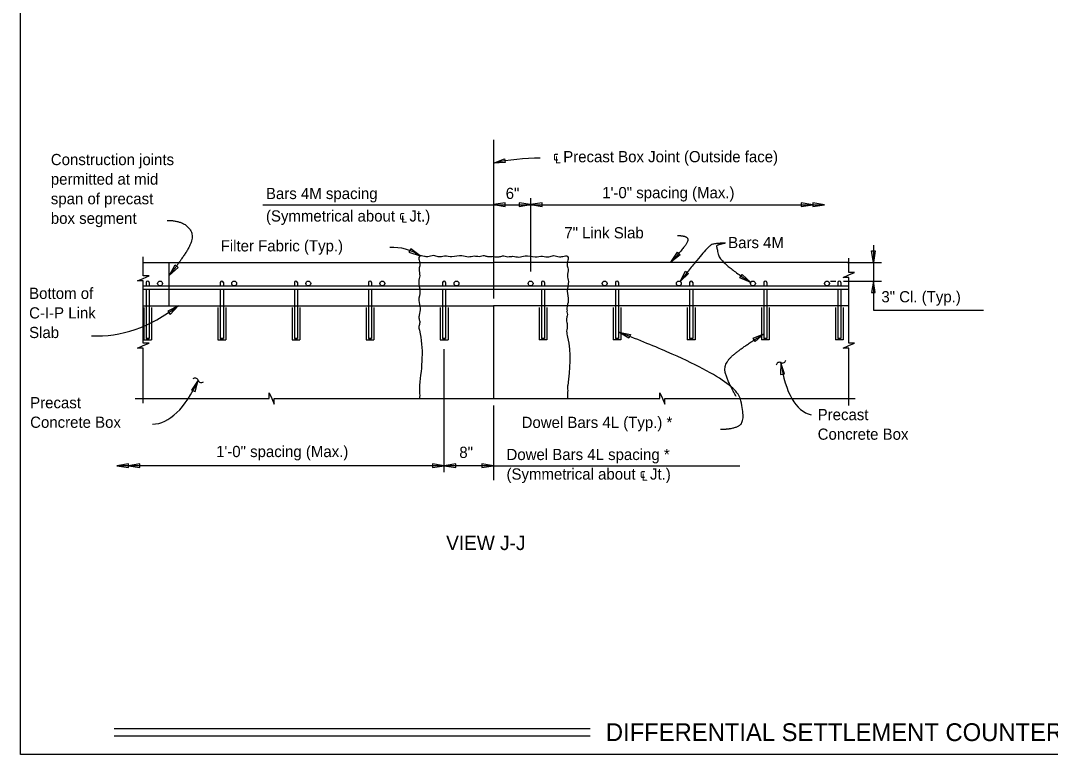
# Model space of a CAD drawing. Extents: x 0 to 30.8, y 0 to 19.8.
# Drawn here: x 0 to 13.9, y 0 to 9.9 of the extents above; entities that cross this region are included whole.
import ezdxf

# ---------------------------------------------------------------- set-up
doc = ezdxf.new("R2010")
doc.units = 0
for name, color, linetype in [('CL_Major', 7, 'Continuous'), ('Dimension', 7, 'Continuous'), ('Miscellaneous', 7, 'Continuous'), ('Miscellaneous1', 7, 'Continuous'), ('Rebar', 7, 'Continuous'), ('SubStrConc', 7, 'Continuous'), ('SubStrConc_h', 7, 'Continuous'), ('TextStructures', 7, 'Continuous')]:
    doc.layers.add(name, color=color, linetype=linetype)

msp = doc.modelspace()

# ---------------------------------------------------------------- linework, layer by layer
at = {"layer": 'CL_Major'}
for p, q in [((6.382, 8.293), (6.382, 6.152)), ((6.382, 4.707), (6.382, 3.699))]:
    msp.add_line(p, q, dxfattribs=at)
at = {"layer": 'Dimension'}
for p, q in [((3.267, 7.416), (6.382, 7.416)), ((6.382, 7.416), (10.846, 7.416)), ((6.882, 7.504), (6.882, 6.514)), ((11.508, 6.872), (11.508, 5.993)), ((11.16, 6.636), (11.618, 6.636)), ((10.929, 6.386), (11, 6.386)), ((11.106, 6.386), (11.618, 6.386)), ((11.508, 5.993), (12.995, 5.993)), ((5.715, 3.808), (5.715, 5.465)), ((6.382, 3.895), (1.299, 3.895)), ((6.382, 3.895), (9.705, 3.895)), ((1.261, 0.35), (7.688, 0.35)), ((1.261, 0.25), (7.688, 0.25))]:
    msp.add_line(p, q, dxfattribs=at)
for points in [[(0, 19.46), (30.788, 19.46), (30.788, 0), (0, 0)], [(6.382, 7.977), (6.529, 8.036), (6.54, 7.984)], [(6.382, 7.417), (6.538, 7.39), (6.538, 7.443)], [(6.882, 7.417), (6.726, 7.443), (6.726, 7.39)], [(6.882, 7.417), (7.038, 7.39), (7.038, 7.443)], [(10.69, 7.416), (10.534, 7.443), (10.534, 7.39)], [(10.846, 7.416), (10.69, 7.443), (10.69, 7.39)], [(5.391, 6.726), (5.266, 6.823), (5.241, 6.776)], [(8.902, 6.738), (8.775, 6.643), (8.863, 6.774)], [(11.508, 6.636), (11.482, 6.792), (11.534, 6.792)], [(2.127, 6.57), (2.008, 6.466), (2.086, 6.603)], [(9.015, 6.488), (8.899, 6.38), (8.974, 6.52)], [(9.735, 6.476), (9.852, 6.368), (9.706, 6.431)], [(11.508, 6.386), (11.482, 6.23), (11.534, 6.23)], [(2.126, 6.052), (1.985, 5.979), (2.018, 5.937)], [(8.209, 5.616), (8.073, 5.697), (8.228, 5.666)], [(9.885, 5.616), (10.031, 5.675), (9.912, 5.571)], [(10.261, 5.285), (10.256, 5.127), (10.309, 5.134)], [(2.395, 5.047), (2.307, 4.916), (2.355, 4.894)], [(1.299, 3.895), (1.455, 3.869), (1.455, 3.922)], [(1.455, 3.895), (1.611, 3.869), (1.611, 3.922)], [(5.715, 3.895), (5.559, 3.922), (5.559, 3.869)], [(5.715, 3.895), (5.872, 3.869), (5.872, 3.922)], [(6.382, 3.895), (6.226, 3.922), (6.226, 3.869)]]:
    msp.add_lwpolyline(points, close=True, dxfattribs=at)
for points in [[(1.656, 6.052), (1.656, 6.387), (1.578, 6.387), (1.656, 6.421), (1.733, 6.455), (1.656, 6.455), (1.656, 6.714)], [(11.175, 6.052), (11.175, 6.435), (11.098, 6.435), (11.175, 6.469), (11.253, 6.502), (11.175, 6.502), (11.175, 6.696)], [(1.656, 4.737), (1.656, 5.482), (1.578, 5.482), (1.656, 5.516), (1.733, 5.55), (1.656, 5.55), (1.656, 6.052)], [(11.175, 4.706), (11.175, 5.482), (11.098, 5.482), (11.175, 5.516), (11.253, 5.55), (11.175, 5.55), (11.175, 6.052)], [(1.547, 4.801), (3.356, 4.801), (3.356, 4.878), (3.39, 4.801), (3.423, 4.723), (3.423, 4.801), (6.382, 4.801)], [(6.382, 4.801), (8.627, 4.801), (8.627, 4.878), (8.66, 4.801), (8.694, 4.723), (8.694, 4.801), (11.263, 4.801)]]:
    msp.add_lwpolyline(points, dxfattribs=at)
for centre, radius, start, end in [((7.023, 5.008), 3.037, 90.1862, 102.1882), ((5.02, 6.182), 0.658, 55.6058, 93.4311), ((10.24, 5.246), 0.0447, 61.6836, 173.4108), ((10.282, 5.325), 0.0447, 241.6836, 353.4108), ((2.353, 5.032), 0.0447, 19.8148, 131.542), ((2.437, 5.062), 0.0447, 199.8148, 311.542)]:
    msp.add_arc(centre, radius, start, end, dxfattribs=at)
for centre, major_axis, ratio, start_param, end_param in [((1.12, 13.945), (0.099, 8.299), 0.422031, 3.123668, 3.460947), ((11.093, 6.474), (0.427, 1.891), 0.393692, 2.335904, 3.141593), ((1.717, 7.141), (-0.061, 2.686), 0.379091, 3.141593, 3.809705)]:
    msp.add_ellipse(centre, major_axis=major_axis, ratio=ratio, start_param=start_param, end_param=end_param, dxfattribs=at)
for points in [[(1.98, 7.204), (2.186, 7.204), (2.361, 6.994), (2.166, 6.66), (2.008, 6.466)], [(8.866, 7), (9.005, 7), (9.005, 6.885), (8.775, 6.643)], [(9.511, 6.897), (9.39, 6.897), (9.271, 6.862), (8.899, 6.38)], [(9.511, 6.897), (9.392, 6.875), (9.392, 6.838), (9.445, 6.633), (9.852, 6.368)], [(9.443, 4.387), (9.637, 4.387), (9.788, 4.51), (9.629, 5.098), (8.073, 5.697)], [(9.658, 4.828), (9.558, 4.994), (9.471, 5.264), (9.752, 5.503), (10.031, 5.675)]]:
    msp.add_open_spline(points, degree=2, dxfattribs=at)
at = {"layer": 'Miscellaneous'}
for points in [[(6.382, 6.719), (6.307, 6.713), (6.261, 6.725), (6.187, 6.715), (6.12, 6.72), (6.042, 6.71), (5.956, 6.727), (5.821, 6.713), (5.721, 6.722), (5.636, 6.712), (5.572, 6.729), (5.494, 6.713), (5.449, 6.719), (5.382, 6.719), (5.375, 6.683), (5.382, 6.652), (5.389, 6.609), (5.377, 6.547), (5.386, 6.458), (5.372, 6.38), (5.389, 6.248), (5.374, 6.124), (5.393, 6.02), (5.379, 5.927), (5.377, 5.878), (5.387, 5.826), (5.375, 5.775), (5.382, 5.722), (5.382, 4.979)], [(6.382, 6.719), (6.457, 6.713), (6.504, 6.725), (6.577, 6.715), (6.644, 6.72), (6.723, 6.71), (6.808, 6.727), (6.944, 6.713), (7.043, 6.722), (7.129, 6.712), (7.192, 6.729), (7.271, 6.713), (7.315, 6.719), (7.382, 6.719), (7.389, 6.683), (7.382, 6.652), (7.375, 6.609), (7.387, 6.547), (7.379, 6.458), (7.392, 6.38), (7.375, 6.248), (7.391, 6.124), (7.372, 6.02), (7.376, 5.986)], [(7.366, 5.986), (7.372, 5.969), (7.379, 5.933), (7.372, 5.902), (7.365, 5.859), (7.377, 5.797), (7.368, 5.708), (7.382, 5.63), (7.383, 4.979)], [(5.382, 4.979), (5.382, 4.972), (5.382, 4.886), (5.386, 4.846), (5.38, 4.801)], [(7.383, 4.979), (7.382, 4.972), (7.382, 4.886), (7.378, 4.846), (7.384, 4.801)]]:
    msp.add_spline(points, degree=3, dxfattribs=at)
at = {"layer": 'Miscellaneous1'}
msp.add_lwpolyline([(0, 19.8), (30.8, 19.8), (30.8, 0), (0, 0)], close=True, dxfattribs=at)
at = {"layer": 'Rebar'}
for p, q in [((1.656, 6.32), (11.175, 6.32)), ((1.656, 6.278), (11.175, 6.278)), ((1.695, 6.365), (1.695, 6.32)), ((1.695, 6.278), (1.695, 5.612)), ((1.736, 6.365), (1.736, 6.32)), ((1.736, 6.278), (1.736, 5.612)), ((2.695, 6.365), (2.695, 6.32)), ((2.695, 6.278), (2.695, 5.612)), ((2.736, 6.365), (2.736, 6.32)), ((2.736, 6.278), (2.736, 5.612)), ((3.695, 6.365), (3.695, 6.32)), ((3.695, 6.278), (3.695, 5.612)), ((3.736, 6.365), (3.736, 6.32)), ((3.736, 6.278), (3.736, 5.612)), ((4.695, 6.365), (4.695, 6.32)), ((4.695, 6.278), (4.695, 5.612)), ((4.736, 6.365), (4.736, 6.32)), ((4.736, 6.278), (4.736, 5.612)), ((5.695, 6.365), (5.695, 6.32)), ((5.695, 6.278), (5.695, 5.612)), ((5.736, 6.365), (5.736, 6.32)), ((5.736, 6.278), (5.736, 5.612)), ((7.028, 6.365), (7.028, 6.32)), ((7.028, 6.278), (7.028, 5.612)), ((7.07, 6.365), (7.07, 6.32)), ((7.07, 6.278), (7.07, 5.612)), ((8.028, 6.365), (8.028, 6.32)), ((8.028, 6.278), (8.028, 5.612)), ((8.07, 6.365), (8.07, 6.32)), ((8.07, 6.278), (8.07, 5.612)), ((9.028, 6.365), (9.028, 6.32)), ((9.028, 6.278), (9.028, 5.612)), ((9.07, 6.365), (9.07, 6.32)), ((9.07, 6.278), (9.07, 5.612)), ((10.028, 6.365), (10.028, 6.32)), ((10.028, 6.278), (10.028, 5.612)), ((10.07, 6.365), (10.07, 6.32)), ((10.07, 6.278), (10.07, 5.612)), ((11.028, 6.365), (11.028, 6.32)), ((11.028, 6.278), (11.028, 5.612)), ((11.07, 6.365), (11.07, 6.32)), ((11.07, 6.278), (11.07, 5.612)), ((1.695, 5.612), (1.736, 5.612)), ((1.736, 5.612), (1.695, 5.612)), ((2.695, 5.612), (2.736, 5.612)), ((2.736, 5.612), (2.695, 5.612)), ((3.695, 5.612), (3.736, 5.612)), ((3.736, 5.612), (3.695, 5.612)), ((4.695, 5.612), (4.736, 5.612)), ((4.736, 5.612), (4.695, 5.612)), ((5.695, 5.612), (5.736, 5.612)), ((5.736, 5.612), (5.695, 5.612)), ((7.07, 5.612), (7.028, 5.612)), ((7.028, 5.612), (7.07, 5.612)), ((8.07, 5.612), (8.028, 5.612)), ((8.028, 5.612), (8.07, 5.612)), ((9.07, 5.612), (9.028, 5.612)), ((9.028, 5.612), (9.07, 5.612)), ((10.07, 5.612), (10.028, 5.612)), ((10.028, 5.612), (10.07, 5.612)), ((11.07, 5.612), (11.028, 5.612)), ((11.028, 5.612), (11.07, 5.612))]:
    msp.add_line(p, q, dxfattribs=at)
for centre in [(1.882, 6.353), (2.882, 6.353), (3.882, 6.353), (4.882, 6.353), (5.882, 6.353), (6.882, 6.353), (7.882, 6.353), (8.882, 6.353), (9.882, 6.353), (10.882, 6.353)]:
    msp.add_circle(centre, 0.0328, dxfattribs=at)
for centre in [(1.715, 6.365), (2.715, 6.365), (3.715, 6.365), (4.715, 6.365), (5.715, 6.365), (7.049, 6.365), (8.049, 6.365), (9.049, 6.365), (10.049, 6.365), (11.049, 6.365)]:
    msp.add_arc(centre, 0.0209, 0, 180, dxfattribs=at)
at = {"layer": 'SubStrConc'}
for p, q in [((1.656, 6.636), (6.382, 6.636)), ((11.175, 6.636), (6.382, 6.636)), ((1.656, 6.052), (6.382, 6.052)), ((11.175, 6.052), (6.382, 6.052))]:
    msp.add_line(p, q, dxfattribs=at)
at = {"layer": 'SubStrConc_h'}
for p, q in [((2.002, 6.636), (2.002, 6.052)), ((1.663, 6.029), (1.663, 5.591)), ((1.768, 6.029), (1.768, 5.591)), ((2.663, 6.029), (2.663, 5.591)), ((2.768, 6.029), (2.768, 5.591)), ((3.663, 6.029), (3.663, 5.591)), ((3.768, 6.029), (3.768, 5.591)), ((4.663, 6.029), (4.663, 5.591)), ((4.768, 6.029), (4.768, 5.591)), ((5.663, 6.029), (5.663, 5.591)), ((5.768, 6.029), (5.768, 5.591)), ((6.382, 6.052), (6.382, 4.811)), ((6.997, 6.029), (6.997, 5.591)), ((7.101, 6.029), (7.101, 5.591)), ((7.997, 6.029), (7.997, 5.591)), ((8.101, 6.029), (8.101, 5.591)), ((8.997, 6.029), (8.997, 5.591)), ((9.101, 6.029), (9.101, 5.591)), ((9.997, 6.029), (9.997, 5.591)), ((10.101, 6.029), (10.101, 5.591)), ((10.997, 6.029), (10.997, 5.591)), ((11.101, 6.029), (11.101, 5.591)), ((1.663, 5.591), (1.768, 5.591)), ((2.663, 5.591), (2.768, 5.591)), ((3.663, 5.591), (3.768, 5.591)), ((4.663, 5.591), (4.768, 5.591)), ((5.663, 5.591), (5.768, 5.591)), ((7.101, 5.591), (6.997, 5.591)), ((8.101, 5.591), (7.997, 5.591)), ((9.101, 5.591), (8.997, 5.591)), ((10.101, 5.591), (9.997, 5.591)), ((11.101, 5.591), (10.997, 5.591))]:
    msp.add_line(p, q, dxfattribs=at)

# ---------------------------------------------------------------- texts
at = {"layer": 'Dimension'}
for s, height, p in [('Construction joints', 0.1512, (0.408, 7.95)), ('℄ Precast Box Joint (Outside face)', 0.1512, (7.184, 7.989)), ('permitted at mid', 0.1512, (0.408, 7.686)), ('Bars 4M spacing ', 0.1512, (3.311, 7.492)), ('6"', 0.1512, (6.546, 7.494)), ('span of precast', 0.1512, (0.408, 7.422)), ('box segment', 0.1512, (0.408, 7.158)), ('(Symmetrical about ℄ Jt.)', 0.1512, (3.311, 7.189)), ('7" Link Slab', 0.1512, (7.337, 6.962)), ('Bottom of', 0.1512, (0.115, 6.145)), ('3" Cl. (Typ.)', 0.1512, (11.616, 6.099)), ('C-I-P Link', 0.1512, (0.115, 5.881)), ('Slab', 0.1512, (0.115, 5.617)), ('8"', 0.1512, (5.92, 3.999)), ('Dowel Bars 4L spacing *', 0.1512, (6.557, 3.971)), ('(Symmetrical about ℄ Jt.)', 0.1512, (6.557, 3.707)), ('VIEW J-J', 0.192, (5.743, 2.757))]:
    msp.add_text(s, height=height, dxfattribs=at).set_placement(p)
at = {"layer": 'TextStructures'}
for s, height, p in [('1\'-0" spacing (Max.)', 0.1512, (7.849, 7.504)), ('Bars 4M', 0.1512, (9.548, 6.83)), ('Filter Fabric (Typ.)', 0.1512, (2.7, 6.786)), ('Precast', 0.1512, (0.129, 4.67)), ('Precast', 0.1512, (10.756, 4.509)), ('Concrete Box', 0.1512, (0.129, 4.406)), ('Dowel Bars 4L (Typ.) *', 0.1512, (6.761, 4.404)), ('Concrete Box', 0.1512, (10.756, 4.245)), ('1\'-0" spacing (Max.)', 0.1512, (2.638, 4.011)), ('DIFFERENTIAL SETTLEMENT COUNTERMEASURES FOR PRECAST BOX CULVERTS', 0.24, (7.898, 0.18))]:
    msp.add_text(s, height=height, dxfattribs=at).set_placement(p)

doc.saveas('drawing.dxf')
